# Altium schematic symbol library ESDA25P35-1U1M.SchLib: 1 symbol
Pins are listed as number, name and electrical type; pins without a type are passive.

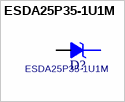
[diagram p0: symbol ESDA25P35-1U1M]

## ESDA25P35-1U1M
designator D?
footprint ST_1610
pins: 1 K, 2 A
